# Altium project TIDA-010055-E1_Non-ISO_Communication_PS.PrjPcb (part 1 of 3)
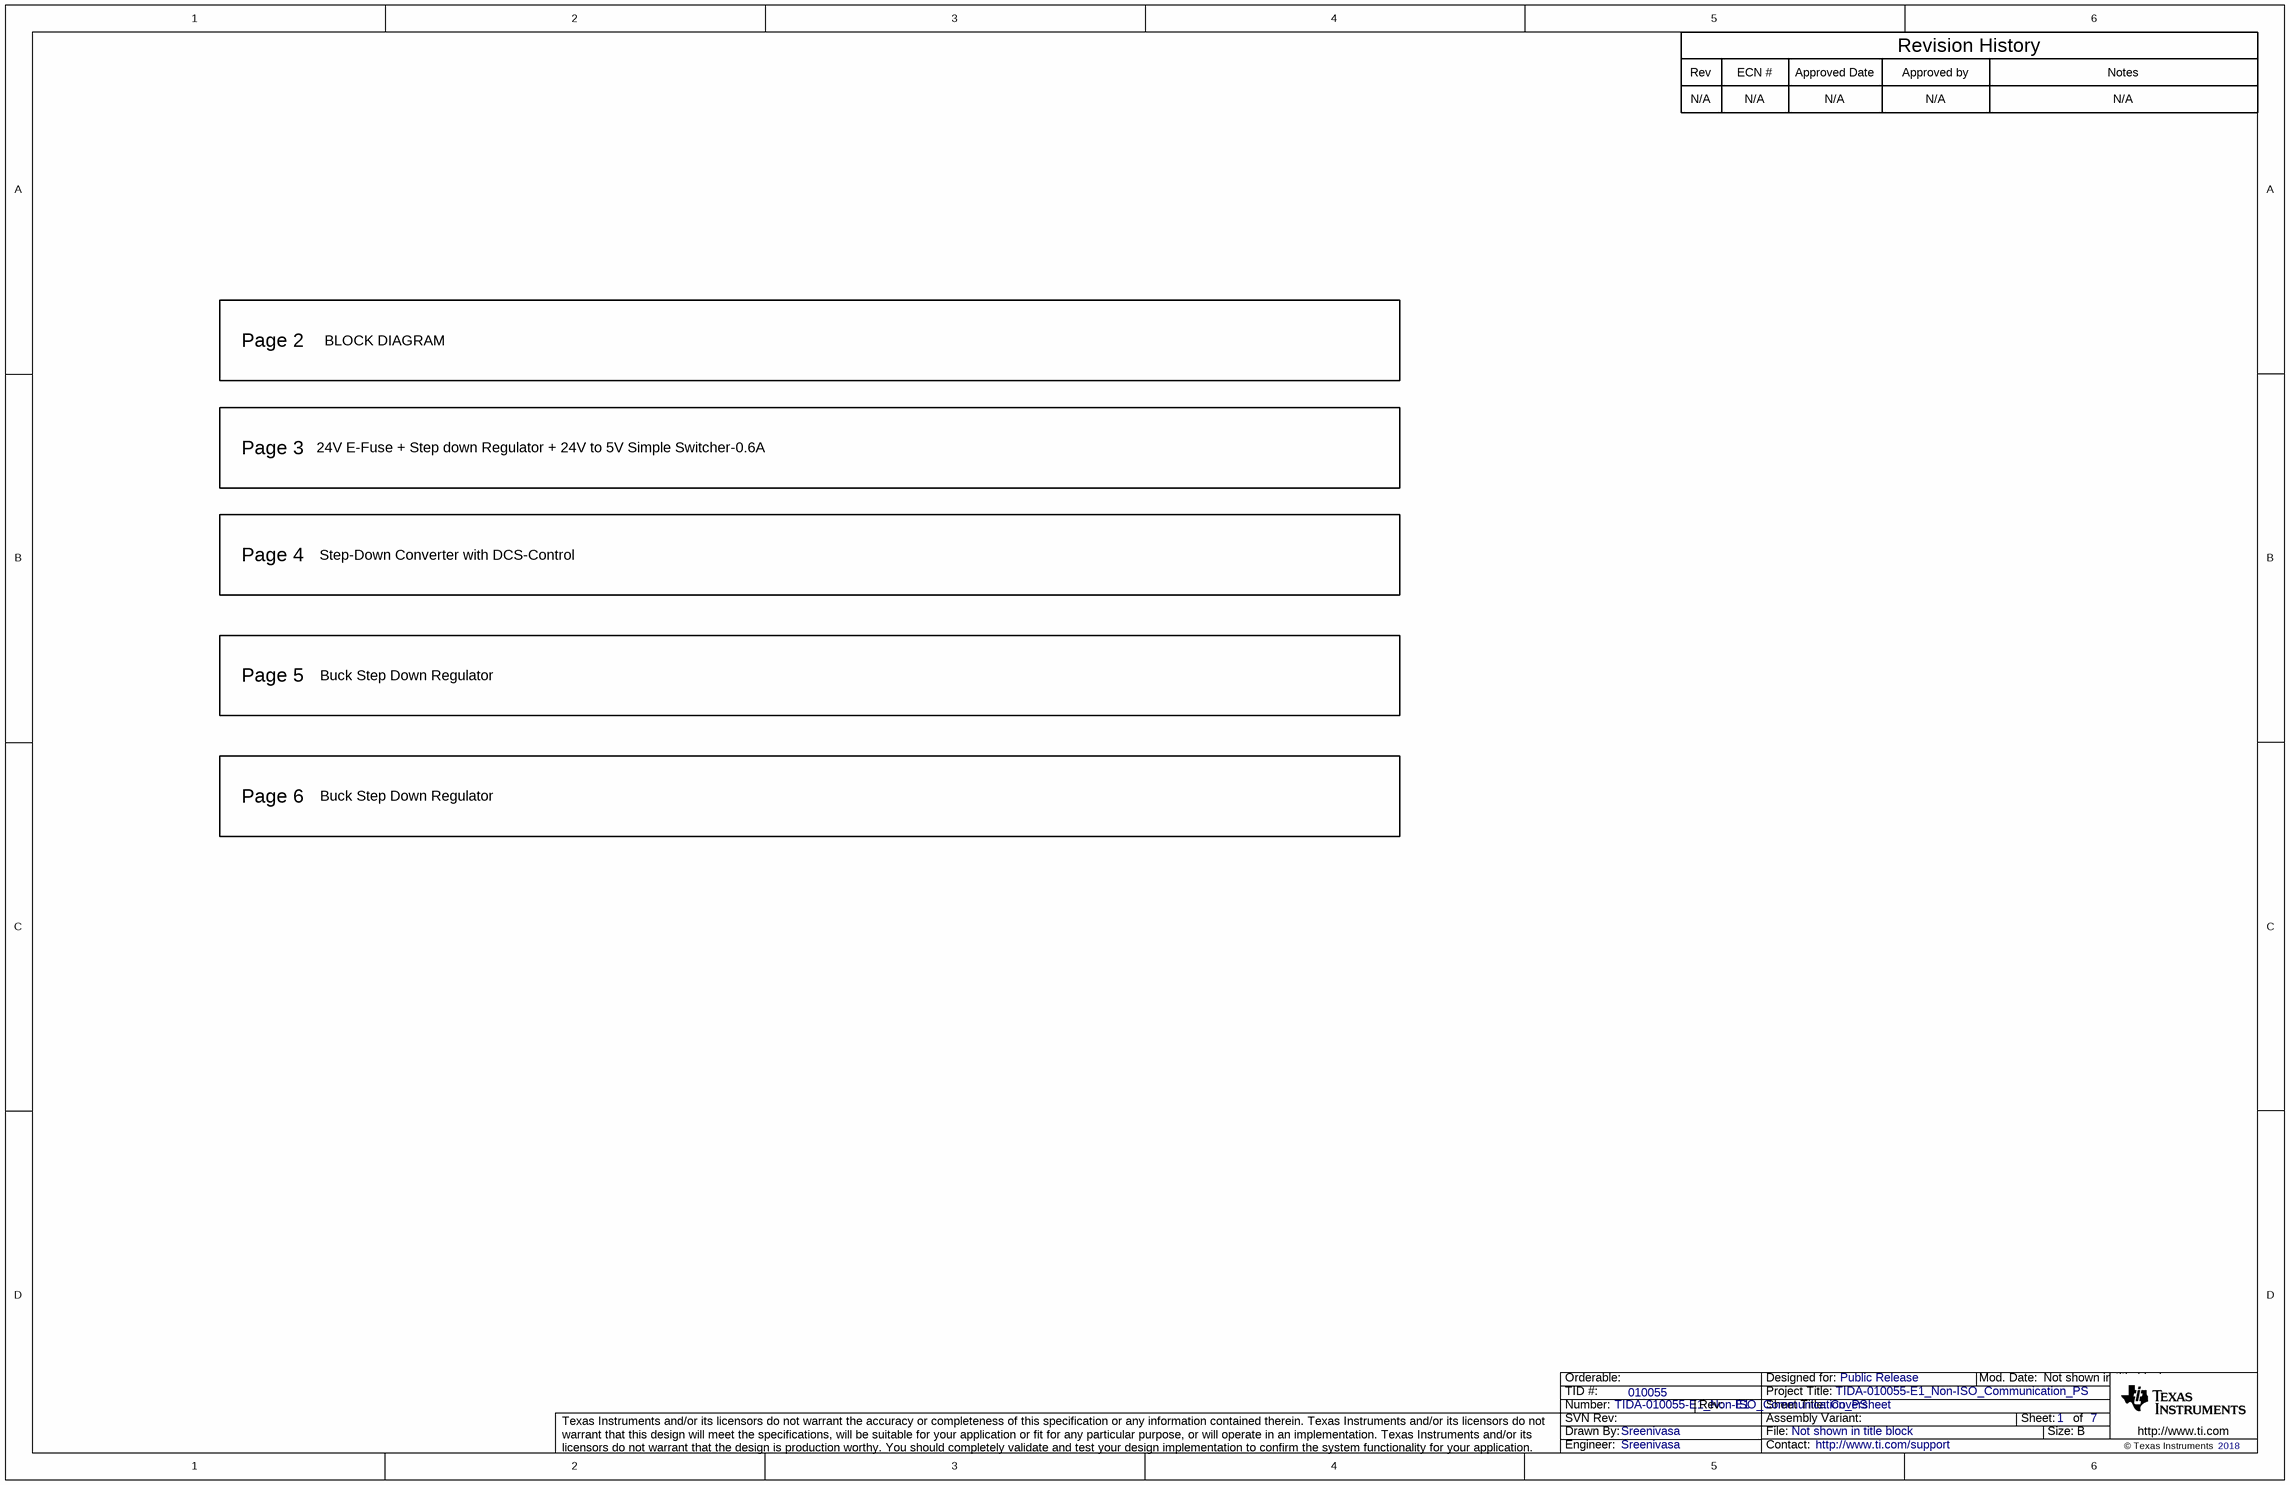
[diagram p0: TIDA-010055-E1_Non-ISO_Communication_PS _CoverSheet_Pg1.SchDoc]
CopyrightYear: 2018; PCB_Layout: Avinash N; PCB_Rev: E1; PRJ_Customer: Public Release; PRJ_Engineer: Sreenivasa; PRJ_Number: TIDA-010055-E1_Non-ISO_Communication_PS; PRJ_Title: TIDA-010055-E1_Non-ISO_Communication_PS; SCH_Rev: E1; TechSupport: http://www.ti.com/support; TID: 010055
7 sheets, 329 parts. Net scope: global (net labels, ports and power ports of the same name join across sheets).
Board file: TIDA-010055-E1_Non-ISO_Communication_PS.PcbDoc
Sheets:
  TIDA-010055-E1_Non-ISO_Communication_PS _CoverSheet_Pg1.SchDoc
  TIDA-010055-E1_Non-ISO_Communication_PS _ Block Diagram_Pg2.SchDoc
  TIDA-010055-E1_Non-ISO_Communication_PS_Pg3.SchDoc
  TIDA-010055-E1_Non-ISO_Communication_PS_Pg4.SchDoc
  TIDA-010055-E1_Non-ISO_Communication_PS_Pg5.SchDoc
  TIDA-010055-E1_Non-ISO_Communication_PS_Pg6.SchDoc
  TIDA-010055-E1_Non-ISO_Communication_PS_EVM_Hardware_Pg6.SchDoc

## Sheet TIDA-010055-E1_Non-ISO_Communication_PS _CoverSheet_Pg1.SchDoc: Coversheet
size 431 x 279 mm; Date: Not shown in title block; ApprovedBy: Not shown in title block; CheckedBy: Not shown in title block; Author: Not shown in title block; CompanyName: Not shown in title block; DrawnBy: Sreenivasa; Engineer: Not shown in title block; Organization: Not shown in title block; Address1: Not shown in title block; Address2: Not shown in title block; Address3: Not shown in title block; Address4: Not shown in title block; DocumentNumber: 1; Revision: Use project parameter SCH_Rev; SheetNumber: 1; SheetTotal: 7; PageSetup: Record=PageOptions¦CenterHorizontal=True¦CenterVertical=True¦PrintScale=1.00¦XCorrection=1.00¦YCorrection=1.00¦PrintKind=0¦BorderSize=5000000¦LeftOffset=0¦BottomOffset=0¦Orientation=2¦PaperLength=1000¦PaperWidth=1000¦Scale=100¦PaperSource=15¦PrintQuality=600¦MediaType=1¦DitherType=10¦PaperKind=Letter¦PrintScaleMode=1

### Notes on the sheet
- Rev
- N/A
- ECN #
- Approved Date
- Approved by
- Revision History
- Notes
- Page 2
- BLOCK DIAGRAM
- Page 3
- 24V E-Fuse + Step down Regulator + 24V to 5V Simple Switcher-0.6A
- Page 4
- Step-Down Converter with DCS-Control
- Page 5
- Buck Step Down Regulator
- Page 6

## Sheet TIDA-010055-E1_Non-ISO_Communication_PS _ Block Diagram_Pg2.SchDoc: Block Diagram
size 431 x 279 mm; Date: Not shown in title block; ApprovedBy: Not shown in title block; CheckedBy: Not shown in title block; Author: Not shown in title block; CompanyName: Not shown in title block; DrawnBy: Sreenivasa; Engineer: Sreenivasa; Organization: Not shown in title block; Address1: Not shown in title block; Address2: Not shown in title block; Address3: Not shown in title block; Address4: Not shown in title block; DocumentNumber: 1; Revision: Use project parameter SCH_Rev; SheetNumber: 2; SheetTotal: 7; PageSetup: Record=PageOptions¦CenterHorizontal=True¦CenterVertical=True¦PrintScale=1.00¦XCorrection=1.00¦YCorrection=1.00¦PrintKind=0¦BorderSize=5000000¦LeftOffset=0¦BottomOffset=0¦Orientation=2¦PaperLength=1000¦PaperWidth=1000¦Scale=100¦PaperSource=15¦PrintQuality=600¦MediaType=1¦DitherType=10¦PaperKind=Letter¦PrintScaleMode=1
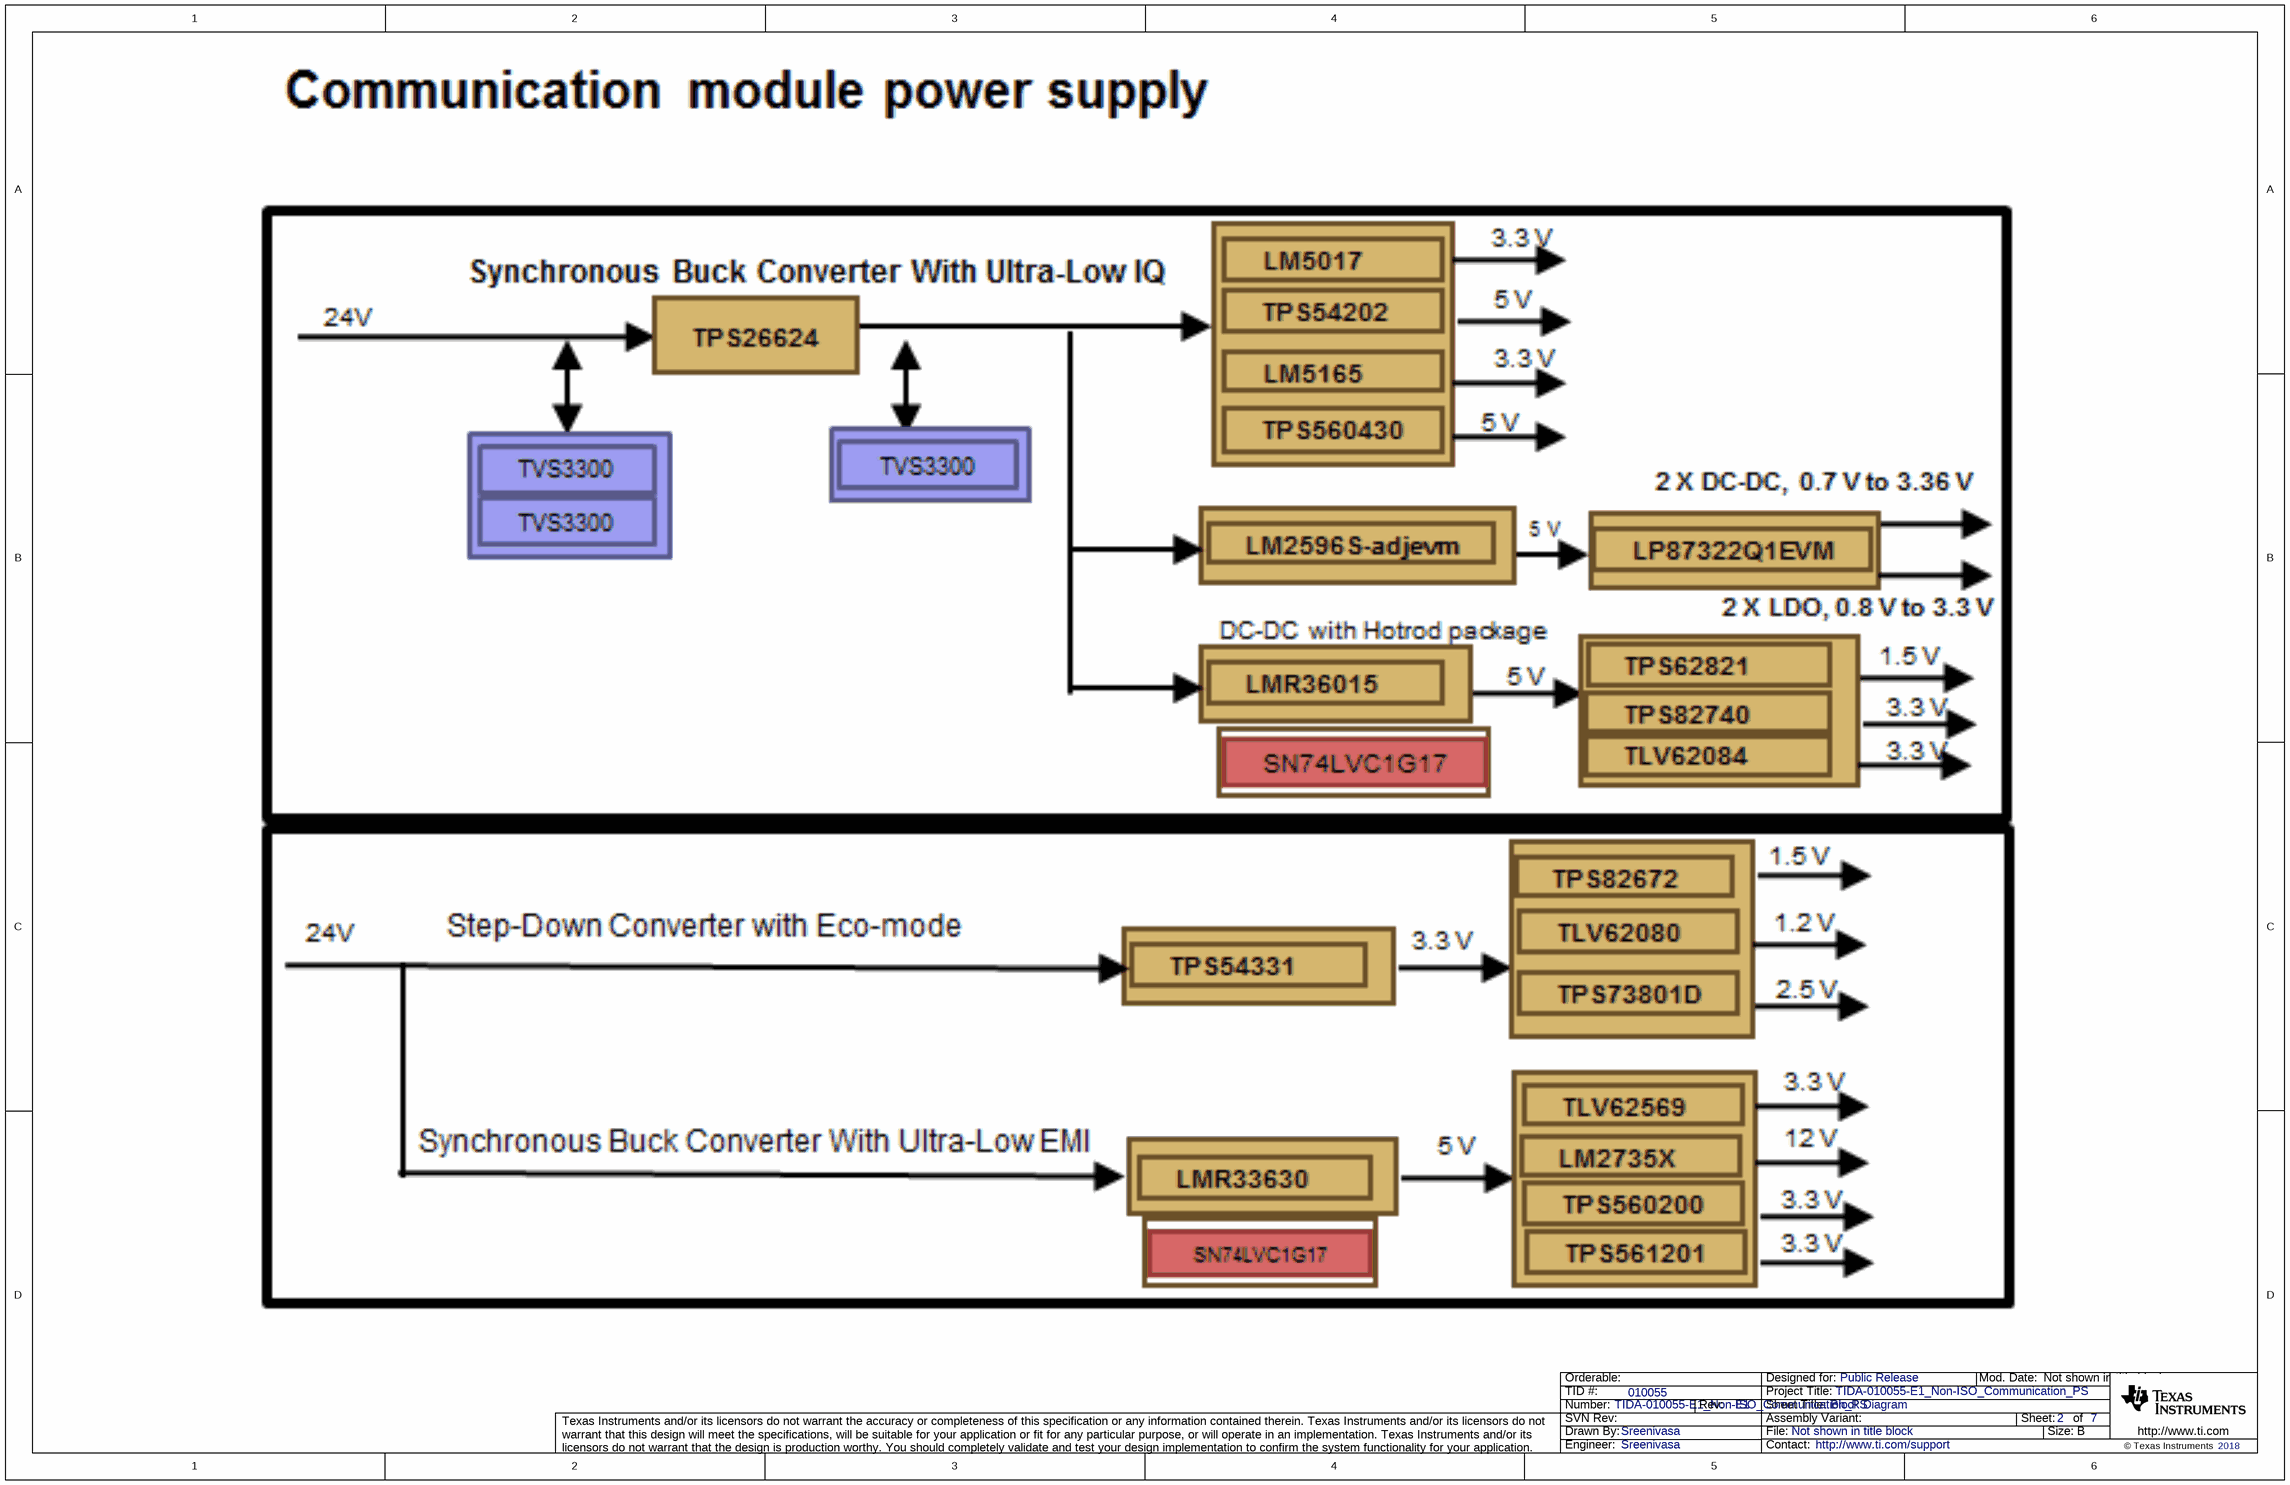
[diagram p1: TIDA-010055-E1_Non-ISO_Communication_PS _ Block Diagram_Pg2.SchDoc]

## Sheet TIDA-010055-E1_Non-ISO_Communication_PS_Pg3.SchDoc: +24V INPUT ISOLATED DC-DC
size 431 x 279 mm; Date: Not shown in title block; ApprovedBy: Not shown in title block; CheckedBy: Not shown in title block; Author: Not shown in title block; CompanyName: Not shown in title block; DrawnBy: Sreenivasa; Engineer: Not shown in title block; Organization: Not shown in title block; Address1: Not shown in title block; Address2: Not shown in title block; Address3: Not shown in title block; Address4: Not shown in title block; DocumentNumber: 1; Revision: Use project parameter SCH_Rev; SheetNumber: 3; SheetTotal: 7; PageSetup: Record=PageOptions¦CenterHorizontal=True¦CenterVertical=True¦PrintScale=0.62¦XCorrection=1.00¦YCorrection=1.00¦PrintKind=0¦BorderSize=5000000¦LeftOffset=0¦BottomOffset=0¦Orientation=2¦PaperLength=1000¦PaperWidth=1000¦Scale=100¦PaperSource=15¦PrintQuality=600¦MediaType=1¦DitherType=10¦PrintScaleMode=1¦PaperKind=Letter
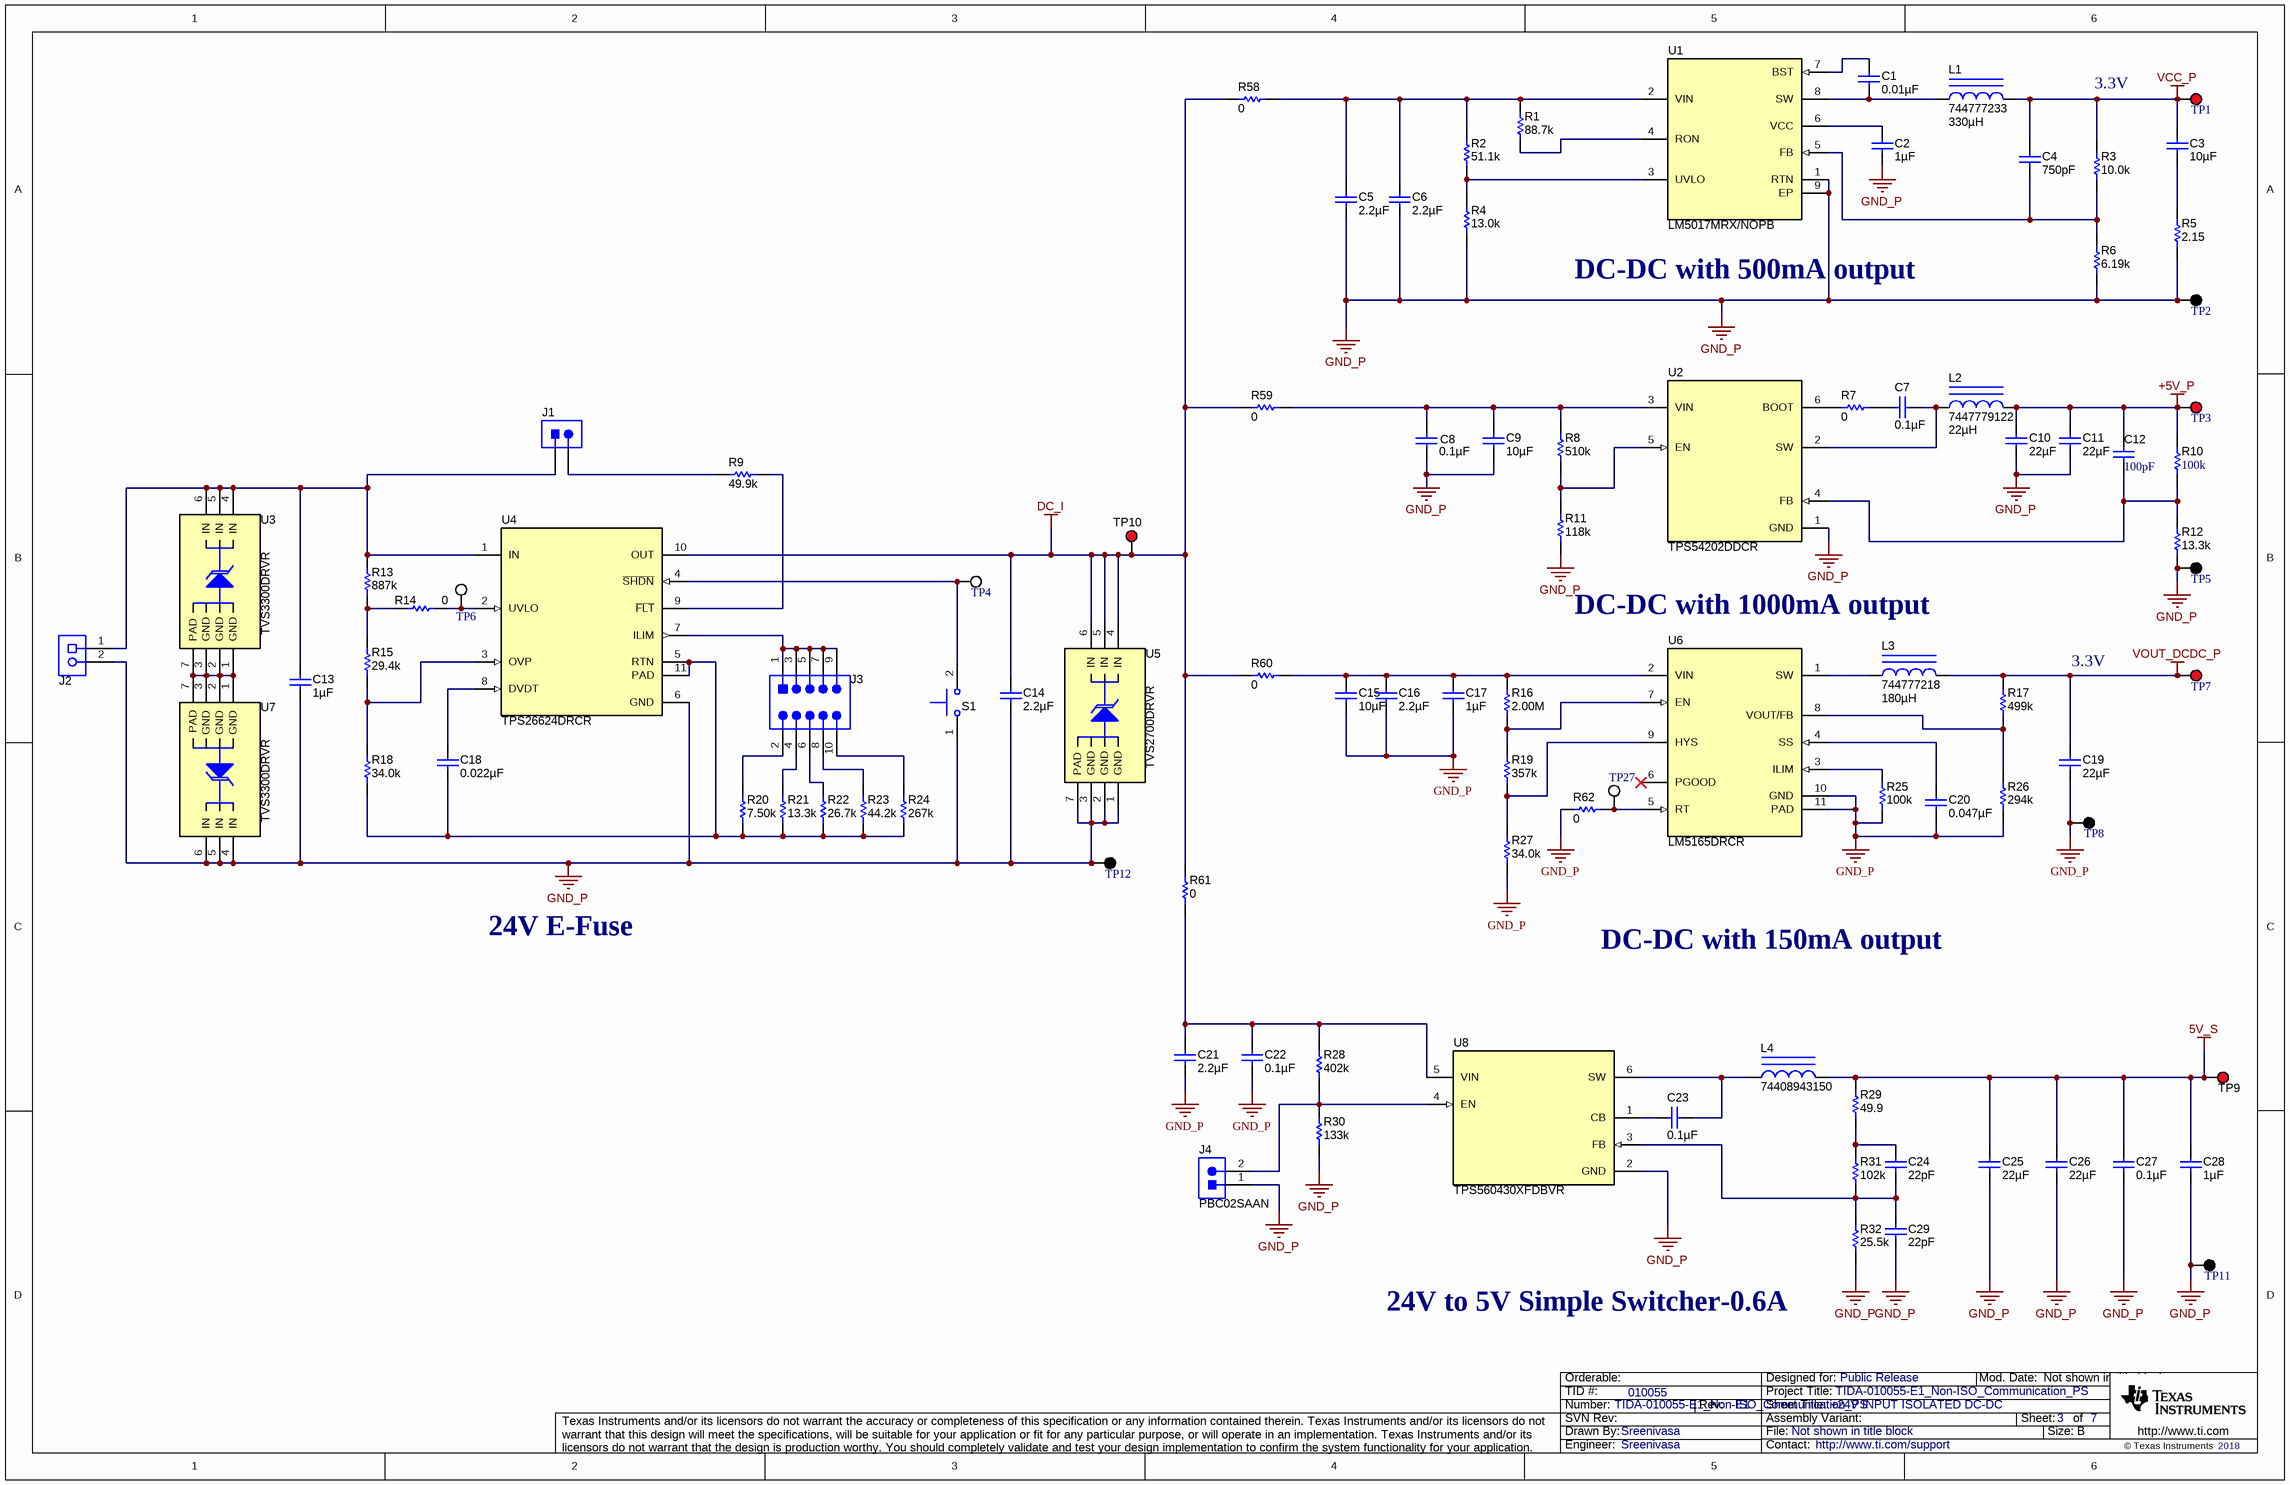
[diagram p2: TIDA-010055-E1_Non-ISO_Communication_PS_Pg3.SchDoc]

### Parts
C1  ValueDisplayed: 0.01µF  [0402]  (hidden comment: C0402C103K4PAC7867)
C2  ValueDisplayed: 1µF  [0603]  (hidden comment: CL10A105KO8NNNC)
C3  ValueDisplayed: 10µF  [0603]  (hidden comment: GRM188R60J106ME47D)
C4  ValueDisplayed: 750pF  [0402]  (hidden comment: C0402C751J5GAC7867)
C5  ValueDisplayed: 2.2µF  [1210_270]  (hidden comment: C3225X7R2A225K230AB)
C6  ValueDisplayed: 2.2µF  [1210_270]  (hidden comment: C3225X7R2A225K230AB)
C7  ValueDisplayed: 0.1µF  [0805_HV]  (hidden comment: C0805C104K3RACTU)
C8  ValueDisplayed: 0.1µF  [0603]  (hidden comment: CL10B104KA8NNNC)
C9  ValueDisplayed: 10µF  [1206]  (hidden comment: CL31B106KAHNNNE)
C10  ValueDisplayed: 22µF  [1206_190]  (hidden comment: GCM31CR71A226KE02)
C11  ValueDisplayed: 22µF  [1206_190]  (hidden comment: GCM31CR71A226KE02)
C12  ValueDisplayed: 100pF  [0603]  (hidden comment: 06033C101KAT2A)
C13  ValueDisplayed: 1µF  [1206_180M]  (hidden comment: C3216X7R2A105K160AA)
C14  ValueDisplayed: 2.2µF  [1210_270]  (hidden comment: C3225X7R2A225K230AB)
C15  ValueDisplayed: 10µF  [1210_270]  (hidden comment: CL32B106KBJNNWE)
C16  ValueDisplayed: 2.2µF  [1206]  (hidden comment: UMK316B7225KL-T)
C17  ValueDisplayed: 1µF  [1206]  (hidden comment: C3216X7R2A105K160AA)
C18  ValueDisplayed: 0.022µF  [0603]  (hidden comment: C0603C223K4RACTU)
C19  ValueDisplayed: 22µF  [1206]  (hidden comment: CL31B226KPHNNNE)
C20  ValueDisplayed: 0.047µF  [0402]  (hidden comment: CL05B473KO5NNNC)
C21  ValueDisplayed: 2.2µF  [1206]  (hidden comment: UMK316B7225KL-T)
C22  ValueDisplayed: 0.1µF  [0603]  (hidden comment: C0603X124K5RAC7867)
C23  ValueDisplayed: 0.1µF  [0603]  (hidden comment: C0603X124K5RAC7867)
C24  ValueDisplayed: 22pF  [0603]  (hidden comment: 06035A220JAT2A)
C25  ValueDisplayed: 22µF  [1206_180]  (hidden comment: CL31B226MPHNNNE)
C26  ValueDisplayed: 22µF  [1206_180]  (hidden comment: CL31B226MPHNNNE)
C27  ValueDisplayed: 0.1µF  [0603]  (hidden comment: C0603X124K5RAC7867)
C28  ValueDisplayed: 1µF  [0603]  (hidden comment: UMK107BJ105KA-T)
C29  ValueDisplayed: 22pF  [0603]  (hidden comment: 06035A220JAT2A)
J1  PBC02SAAN  [Sullins_PBC02SAAN]  (value not drawn)
J2  1751248  [CONN_1751248]  (value not drawn)
J3  PEC05DAAN  [CONN_PEC05DAAN]  (value not drawn)
J4  PBC02SAAN  [Sullins_PBC02SAAN]
L1  744777233  ValueDisplayed: 330µH  [WE-PD-M]
L2  7447779122  ValueDisplayed: 22µH  [WE-PD-M]
L3  744777218  ValueDisplayed: 180µH  [WE-PD-M]
L4  74408943150  [WE-SPC_4838]
R1  ValueDisplayed: 88.7k  [0402]  (hidden comment: CRCW040288K7FKED)
R2  ValueDisplayed: 51.1k  [0402]  (hidden comment: CRCW040251K1FKED)
R3  ValueDisplayed: 10.0k  [0402]  (hidden comment: CRCW040210K0FKED)
R4  ValueDisplayed: 13.0k  [0402]  (hidden comment: CRCW040213K0FKED)
R5  ValueDisplayed: 2.15  [0402]  (hidden comment: CRCW04022R15FKED)
R6  ValueDisplayed: 6.19k  [0805_HV]  (hidden comment: CRCW08056K19FKEA)
R7  ValueDisplayed: 0  [0603]  (hidden comment: CRCW06030000Z0EA)
R8  ValueDisplayed: 510k  [0603]  (hidden comment: CRCW0603510KJNEA)
R9  ValueDisplayed: 49.9k  [0603]  (hidden comment: CRCW060349K9FKEA)
R10  ValueDisplayed: 100k  [0603]  (hidden comment: CRCW0603100KFKEA)
R11  ValueDisplayed: 118k  [0603]  (hidden comment: CRCW0603118KFKEA)
R12  ValueDisplayed: 13.3k  [0603]  (hidden comment: CRCW060313K3FKEA)
R13  ValueDisplayed: 887k  [0603]  (hidden comment: CRCW0603887KFKEA)
R14  ValueDisplayed: 0  [0603]  (hidden comment: CRCW06030000Z0EA)
R15  ValueDisplayed: 29.4k  [0603]  (hidden comment: CRCW060329K4FKEA)
R16  ValueDisplayed: 2.00M  [0402]  (hidden comment: CRCW04022M00FKED)
R17  ValueDisplayed: 499k  [0402]  (hidden comment: CRCW0402499KFKED)
R18  ValueDisplayed: 34.0k  [0603]  (hidden comment: CRCW060334K0FKEA)
R19  ValueDisplayed: 357k  [0402]  (hidden comment: CRCW0402357KFKED)
R20  ValueDisplayed: 7.50k  [0603]  (hidden comment: CRCW06037K50FKEA)
R21  ValueDisplayed: 13.3k  [0603]  (hidden comment: CRCW060313K3FKEA)
R22  ValueDisplayed: 26.7k  [0603]  (hidden comment: CRCW060326K7FKEA)
R23  ValueDisplayed: 44.2k  [0603]  (hidden comment: CRCW060344K2FKEA)
R24  ValueDisplayed: 267k  [0603]  (hidden comment: CRCW0603267KFKEA)
R25  ValueDisplayed: 100k  [0402]  (hidden comment: CRCW0402100KFKED)
R26  ValueDisplayed: 294k  [0402]  (hidden comment: CRCW0402294KFKED)
R27  ValueDisplayed: 34.0k  [0402]  (hidden comment: CRCW040234K0FKED)
R28  ValueDisplayed: 402k  [0603]  (hidden comment: CRCW0603402KFKEA)
R29  ValueDisplayed: 49.9  [0603]  (hidden comment: CRCW060349R9FKEA)
R30  ValueDisplayed: 133k  [0603]  (hidden comment: CRCW0603133KFKEA)
R31  ValueDisplayed: 102k  [0603]  (hidden comment: CRCW0603102KFKEA)
R32  ValueDisplayed: 25.5k  [0603]  (hidden comment: CRCW060325K5FKEA)
R58  ValueDisplayed: 0  [5108]  (hidden comment: 5108)
R59  ValueDisplayed: 0  [5108]  (hidden comment: 5108)
R60  ValueDisplayed: 0  [5108]  (hidden comment: 5108)
R61  ValueDisplayed: 0  [5108]  (hidden comment: 5108)
R62  ValueDisplayed: 0  [0603]  (hidden comment: ERJ-3GEY0R00V)
S1  PTS820 J20M SMTR LFS  [SW_PTS820]  (value not drawn)
TP1  5000  [Keystone5000]  (value not drawn)
TP2  5001  [Keystone5001]  (value not drawn)
TP3  5000  [Keystone5000]  (value not drawn)
TP4  5002  [Keystone5002]  (value not drawn)
TP5  5001  [Keystone5001]  (value not drawn)
TP6  5002  [Keystone5002]  (value not drawn)
TP7  5000  [Keystone5000]  (value not drawn)
TP8  5001  [Keystone5001]  (value not drawn)
TP9  5000  [Keystone5000]  (value not drawn)
TP10  5000  [Keystone5000]  (value not drawn)
TP11  5001  [Keystone5001]  (value not drawn)
TP12  5001  [Keystone5001]  (value not drawn)
TP27  5002  [Keystone5002]  (value not drawn)
U1  LM5017MRX/NOPB  [DDA0008B_N]
U2  TPS54202DDCR  [DDC0006A_N]
U3  TVS3300DRVR  [DRV0006A]
U4  TPS26624DRCR  [DRC0010J]
U5  TVS2700DRVR  [DRV0006A]
U6  LM5165DRCR  [DRC0010J]
U7  TVS3300DRVR  [DRV0006A]
U8  TPS560430XFDBVR  [DBV0006A_N]

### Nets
5V_S: C25.1 C26.1 C27.2 C28.1 L4.2 R29.2 TP9.1
+5V_P: C10.1 C11.1 C12.1 L2.2 R10.2 TP3.1
DC_I: C14.1 R58.1 R59.1 R60.1 R61.1 TP10.1 U4.10(OUT) U5.4(IN) U5.5(IN) U5.6(IN)
GND_P: C2.2 C5.1 C6.1 C8.2 C9.2 C10.2 C11.2 C13.2 C14.2 C15.2 C16.2 C17.2 C19.2 C20.2 C21.2 C22.2 C25.2 C26.2 C27.1 C28.2 C29.2 J2.2 J4.1 R4.1 R5.1 R6.1 R11.1 R12.1 R25.1 R26.1 R27.1 R30.1 R32.1 R62.1 S1.1 TP2.1 TP5.1 TP8.1 TP11.1 TP12.1 U1.1(RTN) U1.9(EP) U2.1(GND) U4.6(GND) U5.1(GND) U5.2(GND) U5.3(GND) U5.7(PAD) U6.10(GND) U6.11(PAD) U7.4(IN) U7.5(IN) U7.6(IN) U8.2(GND)
VCC_P: C3.1 C4.1 L1.2 R3.2 TP1.1
VOUT_DCDC_P: C19.1 L3.2 R17.2 TP7.1
NetC1_1: C1.1 U1.7(BST)
NetC1_2: C1.2 L1.1 U1.8(SW)
NetC2_1: C2.1 U1.6(VCC)
NetC3_2: C3.2 R5.2
NetC4_2: C4.2 R3.1 R6.2 U1.5(FB)
NetC5_2: C5.2 C6.2 R1.2 R2.2 R58.2 U1.2(VIN)
NetC7_1: C7.1 L2.1 U2.2(SW)
NetC7_2: C7.2 R7.2
NetC8_1: C8.1 C9.1 R8.2 R59.2 U2.3(VIN)
NetC12_2: C12.2 R10.1 R12.2 U2.4(FB)
NetC13_1: C13.1 J1.1 J2.1 R13.2 U3.4(IN) U3.5(IN) U3.6(IN) U4.1(IN)
NetC15_1: C15.1 C16.1 C17.1 R16.2 R60.2 U6.2(VIN)
NetC18_1: C18.1 U4.8(DVDT)
NetC18_2: C18.2 R18.1 R20.1 R21.1 R22.1 R23.1 R24.1 U4.5(RTN) U4.11(PAD)
NetC20_1: C20.1 U6.4(SS)
NetC21_1: C21.1 C22.1 R28.2 R61.2 U8.5(VIN)
NetC23_1: C23.1 U8.1(CB)
NetC23_2: C23.2 L4.1 U8.6(SW)
NetC24_1: C24.1 R29.1 R31.2
NetC24_2: C24.2 C29.1 R31.1 R32.2 U8.3(FB)
NetJ1_2: J1.2 R9.2
NetJ3_1: J3.1 J3.3 J3.5 J3.7 J3.9 U4.7(ILIM)
NetJ3_2: J3.2 R20.2
NetJ3_4: J3.4 R21.2
NetJ3_6: J3.6 R22.2
NetJ3_8: J3.8 R23.2
NetJ3_10: J3.10 R24.2
NetJ4_2: J4.2 R28.1 R30.2 U8.4(EN)
NetL3_1: L3.1 U6.1(SW)
NetR1_1: R1.1 U1.4(RON)
NetR2_1: R2.1 R4.2 U1.3(UVLO)
NetR7_1: R7.1 U2.6(BOOT)
NetR8_1: R8.1 R11.2 U2.5(EN)
NetR9_1: R9.1 U4.9(~{FLT})
NetR13_1: R13.1 R14.1 R15.2
NetR14_2: R14.2 TP6.1 U4.2(UVLO)
NetR15_1: R15.1 R18.2 U4.3(OVP)
NetR16_1: R16.1 R19.2 U6.7(EN)
NetR17_1: R17.1 R26.2 U6.8(VOUT/FB)
NetR19_1: R19.1 R27.2 U6.9(HYS)
NetR25_2: R25.2 U6.3(ILIM)
NetR62_2: R62.2 TP27.1 U6.5(RT)
NetS1_2: S1.2 TP4.1 U4.4(~{SHDN})
NetU3_1: U3.1(GND) U3.2(GND) U3.3(GND) U3.7(PAD) U7.1(GND) U7.2(GND) U7.3(GND) U7.7(PAD)

Not connected (* = marked no-connect by the designer): U6 6(PGOOD)*

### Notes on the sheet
- 3.3V
- DC-DC with 500mA output
- DC-DC with 1000mA output
- 24V E-Fuse
- DC-DC with 150mA output
- (near R32) 24V to 5V Simple Switcher-0.6A

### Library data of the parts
C1 = GRM155R61C103KA01D: CAP, CERM, 0.01 µF, 16 V, +/- 10%, X5R, 0402; Manufacturer: KEMET; Polarized: N; CompType: Capacitor; Value: 0.01uF; U/M: EA; Cap_F: 0.00000001; Tolerance_%: 10; Value1: Unknown; VDC_V: 16; Value2: 16V; TaMin_C: -55; TaMax_C: 85; SizeArea_mm2: 0.5; SizeAreaWB_mm2: 3; SizeX_mm: 1; SizeZ_mm: 0.6; AEC Category: Q200
C2 = GRM188R61C105KA93D: CAP, CERM, 1 µF, 16 V, +/- 10%, X5R, 0603; Manufacturer: Samsung Electro-Mechanics; Polarized: N; CompType: Capacitor; Value: 1uF; U/M: EA; Cap_F: 0.000001; Tolerance_%: 10; Value1: Unknown; VDC_V: 16; Value2: 16V; TaMin_C: -55; TaMax_C: 85; SizeArea_mm2: 1.28; SizeAreaWB_mm2: 4.68; SizeX_mm: 1.6; SizeY_mm: 0.8; SizeZ_mm: 1; AEC Category: Q200
C3 = GRM188R60J106ME47D: CAP, CERM, 10 µF, 6.3 V, +/- 20%, X5R, 0603; Manufacturer: MuRata; Polarized: N; CompType: Capacitor; Value: 10uF; U/M: EA; Cap_F: 0.00001; Tolerance_%: 20; ESR_ohm: 0.009; Value1: 0.009 ohm; VDC_V: 6.3; Value2: 6.3V; IRMS_A: 2.74; TaMin_C: -55; TaMax_C: 125; SizeArea_mm2: 1.28; SizeAreaWB_mm2: 4.68; SizeX_mm: 1.6; SizeY_mm: 0.8; SizeZ_mm: 1; AEC Category: Q200
C4 = GRM1555C1H751JA01D: CAP, CERM, 750 pF, 50 V, +/- 5%, C0G/NP0, 0402; Manufacturer: KEMET; Polarized: N; CompType: Capacitor; Value: 750pF; U/M: EA; Cap_F: 0.00000000075; Tolerance_%: 5; Value1: Unknown; VDC_V: 50; Value2: 50V; TaMin_C: -55; TaMax_C: 125; SizeArea_mm2: 0.5; SizeAreaWB_mm2: 3; SizeX_mm: 1; SizeZ_mm: 0.6; AEC Category: Q200
C5 C6 C14 = GRM32ER72A225KA35L: CAP, CERM, 2.2 µF, 100 V, +/- 10%, X7R, 1210; Manufacturer: TDK Corporation; Polarized: N; CompType: Capacitor; Value: 2.2uF; U/M: EA; Cap_F: 0.0000022; Tolerance_%: 10; ESR_ohm: 0.007; Value1: 0.007 ohm; VDC_V: 100; Value2: 100V; IRMS_A: 4.4; TaMin_C: -55; TaMax_C: 125; Cap_Case: 1210; SizeArea_mm2: 8; SizeAreaWB_mm2: 14.7; SizeX_mm: 3.2; SizeY_mm: 2.5; SizeZ_mm: 2.7; AEC Category: Q200
C7 = GRM21BR71E104KA01L: CAP, CERM, 0.1 µF, 25 V, +/- 10%, X7R, 0805; Manufacturer: KEMET; Polarized: N; CompType: Capacitor; Value: 0.1uF; U/M: EA; Cap_F: 0.0000001; Tolerance_%: 10; Value1: Unknown; VDC_V: 25; Value2: 25V; TaMin_C: -55; TaMax_C: 125; Cap_Case: 0805; AEC Category: Q200
C8 = GRM188R71E104KA01D: CAP, CERM, 0.1 µF, 25 V, +/- 10%, X7R, 0603; Manufacturer: Samsung Electro-Mechanics; Polarized: N; CompType: Capacitor; Value: 0.1uF; U/M: EA; Cap_F: 0.0000001; Tolerance_%: 10; Value1: Unknown; VDC_V: 25; Value2: 25V; TaMin_C: -55; TaMax_C: 125; AEC Category: Q200
C9 = GRM31CR71E106KA12L: CAP, CERM, 10 µF, 25 V, +/- 10%, X7R, 1206; Manufacturer: Samsung Electro-Mechanics; Polarized: N; CompType: Capacitor; Value: 10uF; U/M: EA; Cap_F: 0.00001; Tolerance_%: 10; Value1: Unknown; VDC_V: 25; Value2: 25V; TaMin_C: -55; TaMax_C: 125; Cap_Case: 2220; AEC Category: Q200
C10 C11 = GCM31CR71A226KE02: CAP, CERM, 22 µF, 10 V, +/- 10%, X7R, AEC-Q200 Grade 1, 1206_190; Manufacturer: MuRata; Polarized: N; CompType: Capacitor; Value: 22uF; U/M: EA; Cap_F: 0.000022; Tolerance_%: 10; Value1: Unknown; Value2: 10V; TaMin_C: -55; TaMax_C: 125; Cap_Case: 1206; AEC Category: Q200; AEC Qualified: Y; AEC Grade: 1
C12 = CMP-0006751-4: CAP, CERM, 100 pF, 25 V, +/- 10%, X7R, 0603; Manufacturer: AVX; TaMin_C: -55°C; Polarized: N; SizeAreaWB_mm2: 4.68; Value1: Unknown; U/M: EA; Value: 100pF; TaMax_C: 125°C; SizeZ_mm: 1; SizeX_mm: 1.6; SizeY_mm: 0.8; Value2: 25V; SizeArea_mm2: 1.28; CompType: Capacitor; AEC Category: Q200
C13 = GRM31CR72A105KA01L: CAP, CERM, 1 µF, 100 V, +/- 10%, X7R, 1206; Manufacturer: TDK Corporation; Polarized: N; CompType: Capacitor; Value: 1uF; U/M: EA; Cap_F: 0.000001; Tolerance_%: 10; Value1: Unknown; VDC_V: 100; Value2: 100V; TaMin_C: -55; TaMax_C: 125; Cap_Case: 2220; SizeArea_mm2: 5.12; SizeAreaWB_mm2: 10.92; SizeX_mm: 3.2; SizeY_mm: 1.6; SizeZ_mm: 1.8; AEC Category: Q200
C15 = GRM32ER71J106KA12L: CAP, CERM, 10 µF, 63 V, +/- 10%, X7R, 1210; Manufacturer: Samsung Electro-Mechanics; Polarized: N; CompType: Capacitor; Value: 10uF; U/M: EA; Cap_F: 0.00001; Tolerance_%: 10; Value1: Unknown; VDC_V: 63; Value2: 63V; TaMin_C: -55; TaMax_C: 125; Cap_Case: 1210; SizeArea_mm2: 8; SizeAreaWB_mm2: 14.7; SizeX_mm: 3.2; SizeY_mm: 2.5; SizeZ_mm: 2.7; AEC Category: Q200
C16 = UMK316B7225KL-T: CAP, CERM, 2.2 µF, 50 V, +/- 10%, X7R, 1206; Manufacturer: Taiyo Yuden; Polarized: N; CompType: Capacitor; Value: 2.2uF; U/M: EA; Cap_F: 0.0000022; Tolerance_%: 10; Value1: Unknown; VDC_V: 50; Value2: 50V; TaMin_C: -55; TaMax_C: 125; SizeArea_mm2: 5.12; SizeAreaWB_mm2: 10.92; SizeX_mm: 3.2; SizeY_mm: 1.6; SizeZ_mm: 1.35; AEC Category: Q200
C17 = GRM31CR72A105KA01L: CAP, CERM, 1 µF, 100 V, +/- 10%, X7R, 1206; Manufacturer: TDK Corporation; Polarized: N; CompType: Capacitor; Value: 1uF; U/M: EA; Cap_F: 0.000001; Tolerance_%: 10; Value1: Unknown; VDC_V: 100; Value2: 100V; TaMin_C: -55; TaMax_C: 125; Cap_Case: 2220; AEC Category: Q200
C18 = GRM188R71C223KA01D: CAP, CERM, 0.022 µF, 16 V,+/- 10%, X7R, 0603; Manufacturer: KEMET; Polarized: N; CompType: Capacitor; Value: 0.022uF; U/M: EA; Cap_F: 0.000000022; Tolerance_%: 10; VDC_V: 16; Value2: 16V; TaMin_C: -55; TaMax_C: 125; SizeArea_mm2: 1.28; SizeAreaWB_mm2: 4.68; SizeX_mm: 1.6; SizeY_mm: 0.8; SizeZ_mm: 1; AEC Category: Q200; Green_Lifecycle: Active; Green_REACh: Passed
C19 = GRM31CR71A226KE15L: CAP, CERM, 22 µF, 10 V, +/- 10%, X7R, 1206; Manufacturer: Samsung Electro-Mechanics; Polarized: N; CompType: Capacitor; Value: 22uF; U/M: EA; Cap_F: 0.000022; Tolerance_%: 10; Value1: Unknown; Value2: 10V; TaMin_C: -55; TaMax_C: 125; AEC Category: Q200
C20 = GRM155R71C473KA01D: CAP, CERM, 0.047 µF, 16 V, +/- 10%, X7R, 0402; Manufacturer: Samsung Electro-Mechanics; Polarized: N; CompType: Capacitor; Value: 0.047uF; U/M: EA; Cap_F: 0.000000047; Tolerance_%: 10; Value1: Unknown; VDC_V: 16; Value2: 16V; TaMin_C: -55; TaMax_C: 125; AEC Category: Q200
C21 = UMK316B7225KL-T: CAP, CERM, 2.2 µF, 50 V,+/- 10%, X7R, 1206; Manufacturer: Taiyo Yuden; Polarized: N; CompType: Capacitor; Value: 2.2uF; U/M: EA; Cap_F: 0.0000022; Tolerance_%: 10; VDC_V: 50; Value2: 50V; TaMin_C: -55; TaMax_C: 125; SizeArea_mm2: 5.12; SizeAreaWB_mm2: 10.92; SizeX_mm: 3.2; SizeY_mm: 1.6; SizeZ_mm: 1.35; AEC Category: Q200
C22 C23 C27 = GRM188R71H104KA93D: CAP, CERM, 0.12µF ±10% 50V Ceramic Capacitor X7R 0603; Manufacturer: KEMET; Polarized: N; Value: 0.1uF; U/M: EA; Cap_F: 0.0000001; Tolerance_%: 10; VDC_V: 50; TaMin_C: -55; TaMax_C: 125; SizeArea_mm2: 1.28; SizeAreaWB_mm2: 4.68; SizeX_mm: 1.6; SizeY_mm: 0.8; SizeZ_mm: 1; AEC Category: Q200; Green_Lifecycle: Active; Green_REACh: Passed
C24 C29 = 06035A220JAT2A: CAP, CERM, 22 pF, 50 V,+/- 5%, C0G/NP0, 0603; Manufacturer: AVX; Polarized: N; CompType: Capacitor; Value: 22pF; U/M: EA; Cap_F: 0.000000000022; Tolerance_%: 5; ESR_ohm: 0.259; Value1: 0.259 ohm; VDC_V: 50; Value2: 50V; TaMin_C: -55; TaMax_C: 125; SizeArea_mm2: 1.28; SizeAreaWB_mm2: 4.68; SizeX_mm: 1.6; SizeY_mm: 0.8; SizeZ_mm: 1; AEC Category: Q200; Green_Lifecycle: Active; Green_REACh: Passed
C25 C26 = GRM31CR71A226KE15L: CAP, CERM, 22 µF, 10 V,+/- 10%, X7R, 1206; Manufacturer: Samsung Electro-Mechanics; Polarized: N; CompType: Capacitor; Value: 22uF; U/M: EA; Cap_F: 0.000022; Tolerance_%: 10; Value2: 10V; TaMin_C: -55; TaMax_C: 125; Cap_Case: 1206; SizeArea_mm2: 5.12; SizeAreaWB_mm2: 10.92; SizeX_mm: 3.2; SizeY_mm: 1.6; SizeZ_mm: 1.8; AEC Category: Q200; Green_Lifecycle: Active; Green_REACh: Passed
C28 = UMK107AB7105KA-T: CAP, CERM,  1UF 50V X5R 0603; Manufacturer: Taiyo Yuden; Polarized: N; CompType: Capacitor; U/M: EA; Cap_F: 0.000001; Tolerance_%: 10; VDC_V: 50; TempCo: X7R; TaMin_C: -55; TaMax_C: 125; SizeArea_mm2: 1.28; SizeAreaWB_mm2: 4.68; SizeX_mm: 1.6; SizeY_mm: 0.8; SizeZ_mm: 1; AEC Category: Q200; Green_Lifecycle: Active; Green_REACh: Passed
J1 = PBC02SAAN: Header, 100mil, 2x1, Gold, TH; Manufacturer: Sullins Connector Solutions; SymbolCreator: a0412235; Pitch_mm: 2.54; Gender: Male; Shrouded: N; Row_Count: 1; Current_A: 3; Voltage_V: 1800; Cert_UL: Y
J2 = 1751248: Conn Term Block, 2POS, 3.5mm, TH; Manufacturer: Phoenix Contact; CompType: Terminal Block; SymbolCreator: a0412235
J3 = PEC05DAAN: Header, 100mil, 5x2, Tin, TH; Manufacturer: Sullins Connector Solutions; SymbolCreator: a0412235; Pitch_mm: 2.54; Gender: Male; Shrouded: N; Row_Count: 2; Current_A: 3; Voltage_V: 1800; Cert_UL: Y
J4 = PBC02SAAN: Header, 100mil, 2x1, Gold, TH; Manufacturer: Sullins Connector Solutions; SymbolCreator: a0412235; Pitch_mm: 2.54; Gender: Male; Shrouded: N; Row_Count: 1; Current_A: 3; Voltage_V: 1800; Cert_UL: Y; Green_Lifecycle: Active; Green_REACh: Passed
L1 = 744777233: Inductor, Shielded Drum Core, Metal Composite, 330uH, 0.39A, 1.15 ohm, SMD; Manufacturer: Wurth Elektronik eiSos; Ind_H: 330.0E-6; Imax_A: 0.39; Irms: 0.39A @ 40C rise; Isat: 0.45A @ 10% inductance drop; DCR_ohm: 1.15; U/M: EA
L2 = 7447779122: Inductor, Shielded Drum Core, Ferrite, 22uH, 1.41A, 0.09 ohm, SMD; Manufacturer: Wurth Elektronik eiSos; Ind_H: 22.0E-6; Imax_A: 1.41; Irms: 1.41A @ 40C rise; Isat: 1.7A @ 10% inductance drop; DCR_ohm: 0.09; U/M: EA
L3 = 744777218: Inductor, Shielded Drum Core, Metal Composite, 180uH, 0.51A, 0.68 ohm, SMD; Manufacturer: Wurth Elektronik eiSos; Ind_H: 180.0E-6; Imax_A: 0.51; Irms: 0.51A @ 40C rise; Isat: 0.56A @ 10% inductance drop; DCR_ohm: 0.68; U/M: EA
L4 = CMP-0064461-2: Inductor, Shielded Drum Core, Ferrite, 15 uH, 1.4 A, 0.118 ohm, SMD; Manufacturer: Wurth Elektronik; Isat: 1.7A @ 35% inductance drop; Irms: 1.4A @ 40C rise; Green_Lifecycle: Active; SizeAreaWB_mm2: 33.64; DCR_ohm: 1.18d; Green_REACh: Passed; Value: 15uH; Imax_A: 1.4A; SizeZ_mm: 4.1; SizeX_mm: 4.8; SizeArea_mm2: 23.04; Ind_H: 15µH; AEC Category: Q200
R1 = CRCW040288K7FKED: RES, 88.7 k, 1%, 0.063 W, 0402; Manufacturer: Vishay-Dale; CompType: Resistor; Value: 88.7k; Res_ohm: 88700; Value_Code: 88k7; Tolerance_%: 1; Power_W: 0.063; Value2: 0.063W; VDC_V: 50; TempCo: 100 ppm/C; SizeArea_mm2: 0.5; SizeZ_mm: 0.6; EIA_Code: E96; U/M: EA; AEC Category: Q200
R2 = CRCW040251K1FKED: RES, 51.1 k, 1%, 0.063 W, 0402; Manufacturer: Vishay-Dale; CompType: Resistor; Value: 51.1k; Res_ohm: 51100; Value_Code: 51k1; Tolerance_%: 1; Power_W: 0.063; Value2: 0.063W; VDC_V: 50; TempCo: 100 ppm/C; SizeArea_mm2: 0.5; SizeZ_mm: 0.6; EIA_Code: E96; U/M: EA; AEC Category: Q200
R3 = CRCW040210K0FKED: RES, 10.0 k, 1%, 0.063 W, 0402; Manufacturer: Vishay-Dale; CompType: Resistor; Value: 10.0k; Res_ohm: 10000; Value_Code: 10k0; Tolerance_%: 1; Power_W: 0.063; Value2: 0.063W; VDC_V: 50; TempCo: 100 ppm/C; SizeArea_mm2: 0.5; SizeZ_mm: 0.6; EIA_Code: E96; U/M: EA; AEC Category: Q200
R4 = CRCW040213K0FKED: RES, 13.0 k, 1%, 0.063 W, 0402; Manufacturer: Vishay-Dale; CompType: Resistor; Value: 13.0k; Res_ohm: 13000; Value_Code: 13k0; Tolerance_%: 1; Power_W: 0.063; Value2: 0.063W; VDC_V: 50; TempCo: 100 ppm/C; SizeArea_mm2: 0.5; SizeZ_mm: 0.6; EIA_Code: E96; U/M: EA; AEC Category: Q200
R5 = CRCW04022R15FKED: RES, 2.15, 1%, 0.063 W, 0402; Manufacturer: Vishay-Dale; CompType: Resistor; Value: 2.15; Value_Code: 2R15; Tolerance_%: 1; Power_W: 0.063; Value2: 0.063W; VDC_V: 50; TempCo: 100 ppm/C; SizeArea_mm2: 0.5; SizeZ_mm: 0.6; EIA_Code: E96; U/M: EA; AEC Category: Q200
R6 = CRCW08056K19FKEA: RES, 6.19 k, 1%, 0.125 W, 0805; Manufacturer: Vishay-Dale; CompType: Resistor; Value: 6.19k; Res_ohm: 6190; Value_Code: 6k19; Tolerance_%: 1; Power_W: 0.125; Value2: 0.125W; VDC_V: 150; TempCo: 100 ppm/C; SizeArea_mm2: 2.5; SizeX_mm: 2; SizeY_mm: 1.25; SizeZ_mm: 1.45; EIA_Code: E96; U/M: EA; AEC Category: Q200
R7 = CRCW06030000Z0EA: RES, 0, 5%, 0.1 W, 0603; Manufacturer: Vishay-Dale; CompType: Resistor; Value: 0; Value_Code: 0000; Tolerance_%: 5; Power_W: 0.1; Value2: 0.1W; VDC_V: 75; TempCo: 200 ppm/C; EIA_Code: E24; U/M: EA; AEC Category: Q200
R8 = CRCW0603510KJNEA: RES, 510 k, 5%, 0.1 W, 0603; Manufacturer: Vishay-Dale; CompType: Resistor; Value: 510k; Res_ohm: 510000; Tolerance_%: 5; Power_W: 0.1; Value2: 0.1W; VDC_V: 75; TempCo: 200 ppm/C; EIA_Code: E24; U/M: EA; AEC Category: Q200
R9 = CRCW060349K9FKEA: RES, 49.9 k, 1%, 0.1 W, 0603; Manufacturer: Vishay-Dale; CompType: Resistor; Value: 49.9k; Res_ohm: 49900; Value_Code: 49k9; Tolerance_%: 1; Power_W: 0.1; Value2: 0.1W; VDC_V: 75; TempCo: 100 ppm/C; EIA_Code: E96; U/M: EA; SizeArea_mm2: 1.28; SizeX_mm: 1.6; SizeY_mm: 0.8; AEC Category: Q200; Green_Lifecycle: Active; Green_REACh: Passed
R10 = CMP-0021990-4: RES, 100 k, 1%, 0.1 W, AEC-Q200 Grade 0, 0603; Manufacturer: Vishay-Dale; Power_W: 100mW; TempCo: 100 ppm/C; Value: 100k; EIA_Code: E96; SizeX_mm: 1.6; SizeY_mm: 0.8; SizeZ_mm: 1; Value2: 0.1W; SizeArea_mm2: 1.28; CompType: Resistor; AEC Qualified: Y; VDC_V: 75V; AEC Category: Q200; AEC Grade: 0
R11 = CRCW0603118KFKEA: RES, 118 k, 1%, 0.1 W, 0603; Manufacturer: Vishay-Dale; CompType: Resistor; Value: 118k; Res_ohm: 118000; Tolerance_%: 1; Power_W: 0.1; Value2: 0.1W; VDC_V: 75; TempCo: 100 ppm/C; EIA_Code: E96; U/M: EA; AEC Category: Q200
R12 = CRCW060313K3FKEA: RES, 13.3 k, 1%, 0.1 W, 0603; Manufacturer: Vishay-Dale; CompType: Resistor; Value: 13.3k; Res_ohm: 13300; Value_Code: 13k3; Tolerance_%: 1; Power_W: 0.1; Value2: 0.1W; VDC_V: 75; TempCo: 100 ppm/C; EIA_Code: E96; U/M: EA; AEC Category: Q200
R13 = CRCW0603887KFKEA: RES, 887 k, 1%, 0.1 W, 0603; Manufacturer: Vishay-Dale; CompType: Resistor; Value: 887k; Res_ohm: 887000; Tolerance_%: 1; Power_W: 0.1; Value2: 0.1W; VDC_V: 75; TempCo: 100 ppm/C; SizeArea_mm2: 1.28; SizeX_mm: 1.6; SizeY_mm: 0.8; EIA_Code: E96; U/M: EA; AEC Category: Q200; Green_Lifecycle: Active; Green_REACh: Passed
R14 = CRCW06030000Z0EA: RES, 0, 5%, 0.1 W, 0603; Manufacturer: Vishay-Dale; CompType: Resistor; Value: 0; Value_Code: 0000; Tolerance_%: 5; Power_W: 0.1; Value2: 0.1W; VDC_V: 75; TempCo: 200 ppm/C; EIA_Code: E24; U/M: EA
R15 = CRCW060329K4FKEA: RES, 29.4 k, 1%, 0.1 W, 0603; Manufacturer: Vishay-Dale; CompType: Resistor; Value: 29.4k; Res_ohm: 29400; Value_Code: 29k4; Tolerance_%: 1; Power_W: 0.1; Value2: 0.1W; VDC_V: 75; TempCo: 100 ppm/C; SizeArea_mm2: 1.28; SizeX_mm: 1.6; SizeY_mm: 0.8; EIA_Code: E96; U/M: EA; AEC Category: Q200; Green_Lifecycle: Active; Green_REACh: Passed
R16 = CRCW04022M00FKED: RES, 2.00 M, 1%, 0.063 W, 0402; Manufacturer: Vishay-Dale; CompType: Resistor; Value: 2.00Meg; Res_ohm: 2000000; Value_Code: 2M00; Tolerance_%: 1; Power_W: 0.063; Value2: 0.063W; VDC_V: 50; TempCo: 100 ppm/C; EIA_Code: E96; U/M: EA; AEC Category: Q200
R17 = CRCW0402499KFKED: RES, 499 k, 1%, 0.063 W, 0402; Manufacturer: Vishay-Dale; CompType: Resistor; Value: 499k; Res_ohm: 499000; Tolerance_%: 1; Power_W: 0.063; Value2: 0.063W; VDC_V: 50; TempCo: 100 ppm/C; EIA_Code: E96; U/M: EA; AEC Category: Q200
R18 = CRCW060334K0FKEA: RES, 34.0 k, 1%, 0.1 W, 0603; Manufacturer: Vishay-Dale; CompType: Resistor; Value: 34.0k; Res_ohm: 34000; Value_Code: 34k0; Tolerance_%: 1; Power_W: 0.1; Value2: 0.1W; VDC_V: 75; TempCo: 100 ppm/C; EIA_Code: E96; U/M: EA; SizeArea_mm2: 1.28; SizeX_mm: 1.6; SizeY_mm: 0.8; AEC Category: Q200
R19 = CRCW0402357KFKED: RES, 357 k, 1%, 0.063 W, 0402; Manufacturer: Vishay-Dale; CompType: Resistor; Value: 357k; Res_ohm: 357000; Tolerance_%: 1; Power_W: 0.063; Value2: 0.063W; VDC_V: 50; TempCo: 100 ppm/C; EIA_Code: E96; U/M: EA; AEC Category: Q200
R20 = CRCW06037K50FKEA: RES, 7.50 k, 1%, 0.1 W, 0603; Manufacturer: Vishay-Dale; CompType: Resistor; Value: 7.50k; Res_ohm: 7500; Value_Code: 7k50; Tolerance_%: 1; Power_W: 0.1; Value2: 0.1W; VDC_V: 75; TempCo: 100 ppm/C; SizeArea_mm2: 1.28; SizeX_mm: 1.6; SizeY_mm: 0.8; EIA_Code: E96; U/M: EA; AEC Category: Q200
R21 = CRCW060313K3FKEA: RES, 13.3 k, 1%, 0.1 W, 0603; Manufacturer: Vishay-Dale; CompType: Resistor; Value: 13.3k; Res_ohm: 13300; Value_Code: 13k3; Tolerance_%: 1; Power_W: 0.1; Value2: 0.1W; VDC_V: 75; TempCo: 100 ppm/C; SizeArea_mm2: 1.28; SizeX_mm: 1.6; SizeY_mm: 0.8; EIA_Code: E96; U/M: EA; AEC Category: Q200
R22 = CRCW060326K7FKEA: RES, 26.7 k, 1%, 0.1 W, 0603; Manufacturer: Vishay-Dale; CompType: Resistor; Value: 26.7k; Res_ohm: 26700; Value_Code: 26k7; Tolerance_%: 1; Power_W: 0.1; Value2: 0.1W; VDC_V: 75; TempCo: 100 ppm/C; SizeArea_mm2: 1.28; SizeX_mm: 1.6; SizeY_mm: 0.8; EIA_Code: E96; U/M: EA; AEC Category: Q200
R23 = CRCW060344K2FKEA: RES, 44.2 k, 1%, 0.1 W, 0603; Manufacturer: Vishay-Dale; CompType: Resistor; Value: 44.2k; Res_ohm: 44200; Value_Code: 44k2; Tolerance_%: 1; Power_W: 0.1; Value2: 0.1W; VDC_V: 75; TempCo: 100 ppm/C; SizeArea_mm2: 1.28; SizeX_mm: 1.6; SizeY_mm: 0.8; EIA_Code: E96; U/M: EA; AEC Category: Q200
R24 = CRCW0603267KFKEA: RES, 267 k, 1%, 0.1 W, 0603; Manufacturer: Vishay-Dale; CompType: Resistor; Value: 267k; Res_ohm: 267000; Tolerance_%: 1; Power_W: 0.1; Value2: 0.1W; VDC_V: 75; TempCo: 100 ppm/C; SizeArea_mm2: 1.28; SizeX_mm: 1.6; SizeY_mm: 0.8; EIA_Code: E96; U/M: EA; AEC Category: Q200
R25 = CRCW0402100KFKED: RES, 100 k, 1%, 0.063 W, 0402; Manufacturer: Vishay-Dale; CompType: Resistor; Value: 100k; Res_ohm: 100000; Tolerance_%: 1; Power_W: 0.063; Value2: 0.063W; VDC_V: 50; TempCo: 100 ppm/C; EIA_Code: E96; U/M: EA; AEC Category: Q200
R26 = CRCW0402294KFKED: RES, 294 k, 1%, 0.063 W, 0402; Manufacturer: Vishay-Dale; CompType: Resistor; Value: 294k; Res_ohm: 294000; Tolerance_%: 1; Power_W: 0.063; Value2: 0.063W; VDC_V: 50; TempCo: 100 ppm/C; EIA_Code: E96; U/M: EA; AEC Category: Q200
R27 = CRCW040234K0FKED: RES, 34.0 k, 1%, 0.063 W, 0402; Manufacturer: Vishay-Dale; CompType: Resistor; Value: 34.0k; Res_ohm: 34000; Value_Code: 34k0; Tolerance_%: 1; Power_W: 0.063; Value2: 0.063W; VDC_V: 50; TempCo: 100 ppm/C; EIA_Code: E96; U/M: EA; AEC Category: Q200
R28 = CRCW0603402KFKEA: RES, 402 k, 1%, 0.1 W, 0603; Manufacturer: Vishay-Dale; CompType: Resistor; Value: 402k; Res_ohm: 402000; Tolerance_%: 1; Power_W: 0.1; Value2: 0.1W; VDC_V: 75; TempCo: 100 ppm/C; SizeArea_mm2: 1.28; SizeX_mm: 1.6; SizeY_mm: 0.8; EIA_Code: E96; U/M: EA; AEC Category: Q200; Green_Lifecycle: Active; Green_REACh: Passed
R29 = CRCW060349R9FKEA: RES, 49.9, 1%, 0.1 W, 0603; Manufacturer: Vishay-Dale; CompType: Resistor; Value: 49.9; Value_Code: 49R9; Tolerance_%: 1; Power_W: 0.1; Value2: 0.1W; VDC_V: 75; TempCo: 100 ppm/C; SizeArea_mm2: 1.28; SizeX_mm: 1.6; SizeY_mm: 0.8; EIA_Code: E96; U/M: EA; AEC Category: Q200; Green_Lifecycle: Active; Green_REACh: Passed
R30 = CRCW0603133KFKEA: RES, 133 k, 1%, 0.1 W, 0603; Manufacturer: Vishay-Dale; CompType: Resistor; Value: 133k; Res_ohm: 133000; Tolerance_%: 1; Power_W: 0.1; Value2: 0.1W; VDC_V: 75; TempCo: 100 ppm/C; SizeArea_mm2: 1.28; SizeX_mm: 1.6; SizeY_mm: 0.8; EIA_Code: E96; U/M: EA; AEC Category: Q200; Green_Lifecycle: Active; Green_REACh: Passed
R31 = CRCW0603102KFKEA: RES, 102 k, 1%, 0.1 W, 0603; Manufacturer: Vishay-Dale; CompType: Resistor; Value: 102k; Res_ohm: 102000; Tolerance_%: 1; Power_W: 0.1; Value2: 0.1W; VDC_V: 75; TempCo: 100 ppm/C; SizeArea_mm2: 1.28; SizeX_mm: 1.6; SizeY_mm: 0.8; EIA_Code: E96; U/M: EA; AEC Category: Q200; Green_Lifecycle: Active; Green_REACh: Passed
R32 = CRCW060325K5FKEA: RES, 25.5 k, 1%, 0.1 W, 0603; Manufacturer: Vishay-Dale; CompType: Resistor; Value: 25.5k; Res_ohm: 25500; Value_Code: 25k5; Tolerance_%: 1; Power_W: 0.1; Value2: 0.1W; VDC_V: 75; TempCo: 100 ppm/C; SizeArea_mm2: 1.28; SizeX_mm: 1.6; SizeY_mm: 0.8; EIA_Code: E96; U/M: EA; AEC Category: Q200; Green_Lifecycle: Active; Green_REACh: Passed
R58-R61 = 5108: RES, 0, 1%, 0.5 W, 1206; Manufacturer: Keystone; CompType: Resistor; Value: 0; Tolerance_%: 1; Power_W: 0.5; Value2: 0.5W; TempCo: ppm/C; SizeArea_mm2: 5.185; SizeX_mm: 3.05; SizeY_mm: 1.7; SizeZ_mm: 0.84; U/M: EA; AEC Category: Q200; AEC Qualified: N
R62 = ERJ-3GEY0R00V: RES, 0, 5%, 0.1 W, 0603; Manufacturer: Panasonic; CompType: Resistor; Value: 0; Value_Code: 0000; Tolerance_%: 5; Power_W: 0.1; Value2: 0.1W; VDC_V: 50; TempCo: 600 ppm/C; SizeArea_mm2: 1.28; SizeX_mm: 1.6; SizeY_mm: 0.8; SizeZ_mm: 1; EIA_Code: E24; U/M: EA; AEC Category: Q200; Green_Lifecycle: Active; Green_REACh: Passed
S1 = PTS820 J20M SMTR LFS: Switch, SPST-NO,  Off-Mom, 0.05A, 12VDC, SMD; Manufacturer: C&K Components; SymbolCreator: a0412235; VDC_V: 12; PositionCount: 1; CurrentRating_mA: 50
TP1 TP3 TP7 = 5000: Test Point, Miniature, Red, TH; Manufacturer: Keystone; CompType: Test Point Loop; ContactFinish: Silver; Green_Lifecycle: Active; Green_REACh: Passed
TP2 TP5 TP8 TP11 TP12 = 5001: Test Point, Miniature, Black, TH; Manufacturer: Keystone; CompType: Test Point Loop; ContactFinish: Silver; Green_Lifecycle: Active; Green_REACh: Passed
TP4 TP6 TP27 = 5002: Test Point, Miniature, White, TH; Manufacturer: Keystone; CompType: Test Point Loop; ContactFinish: Silver; Green_Lifecycle: Active; Green_REACh: Passed
TP9 TP10 = 5000: Test Point, Miniature, Red, TH; Manufacturer: Keystone; CompType: Test Point Loop; ContactFinish: Silver
U1 = LM5017MRX/NOPB: 100V, 600mA Constant On-Time Synchronous Buck Regulator, DDA0008B; Alternate PartNumber: LM5017MR/NOPB; Manufacturer: Texas Instruments; SymbolCreator: a0412235; SizeArea_mm2: 31; SizeAreaWB_mm2: 57.4; SizeX_mm: 5; SizeY_mm: 6.2; SizeZ_mm: 1.7; CompType: IC; U/M: EA
U2 = TPS54202DDCR: 4.5-V TO 28-V INPUT, 2-A OUTPUT, EMI FRIENDLY SYNCHRONUOUS STEP-DOWN CONVERTOR, DDC0006A; Alternate PartNumber: TPS54202DDCT; Manufacturer: Texas Instruments; SymbolCreator: a0411947; CompType: IC; U/M: EA
U3 U7 = CMP-0013424-7: 33-V Precision Surge Protection Clamp, DRV0006A (WSON-6); Manufacturer: Texas Instruments; Alternate PartNumber: TVS3300DRVT; SizeX_mm: 2; CompType: IC; SizeZ_mm: 0.8; SizeArea_mm2: 4; SizeAreaWB_mm2: 9; U/M: EA
U4 = TPS26624DRCR: 7V - 57V, 800mA Industrial eFuse with Integrated Reverse Polarity Protection, DRC0010J (VSON-10); Alternate PartNumber: TPS26625DRCR; Manufacturer: Texas Instruments; SymbolCreator: a0411947; SizeArea_mm2: 9; SizeAreaWB_mm2: 16; SizeX_mm: 3; SizeZ_mm: 1; CompType: IC; U/M: EA
U5 = CMP-0077833-1: 27-V Precision Surge Protection Clamp, DRV0006A (WSON-6); Alternate Manufacturer: Texas Instruments; SizeAreaWB_mm2: 9.0; SizeZ_mm: 0.8; SizeX_mm: 2.0; SizeArea_mm2: 4.0; CompType: IC; AEC Qualified: N; AEC Category: Q200
U6 = LM5165DRCR: 3.0-V to 65-V Input, 150-mA Output, Ultra-Low Quiescent (ULQ) Synchronous Step-Down Voltage Regulator, DRC0010J; Alternate PartNumber: LM5165DRCT; Manufacturer: Texas Instruments; SymbolCreator: Altium; CompType: IC; U/M: EA
U8 = CMP-0065098-3: 4V to 36 V 0.6 A Synchronous Step-Down Converter, DBV0006A (SOT-23-6); Manufacturer: Texas Instruments; Alternate PartNumber: TPS560430XFDBVT; SizeX_mm: 2.8; SizeY_mm: 2.9; CompType: IC; SizeZ_mm: 1.45; SizeArea_mm2: 8.12; SizeAreaWB_mm2: 14.82; U/M: EA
